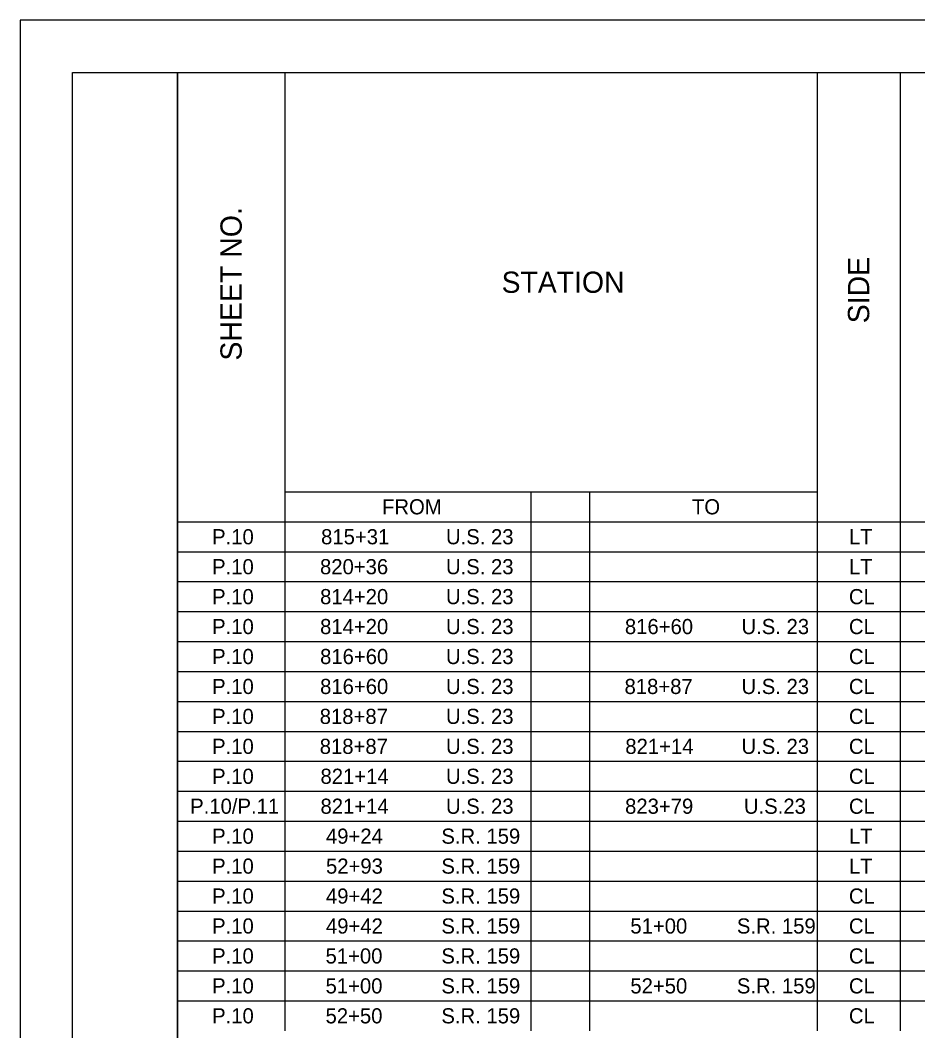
# Model space of a CAD drawing. Extents: x -1022.2 to -988.2, y -965.8 to -943.8.
# Drawn here: x -1022.25 to -1013.68, y -953.43 to -943.79 of the extents above; entities that cross this region are included whole.
import ezdxf

# ---------------------------------------------------------------- set-up
doc = ezdxf.new("R2010")
doc.units = 0
for name, color, linetype in [('Default', 7, 'Continuous'), ('SH_Border', 7, 'Continuous'), ('SH_Cut_Line', 7, 'Continuous')]:
    doc.layers.add(name, color=color, linetype=linetype)

msp = doc.modelspace()

# ---------------------------------------------------------------- linework, layer by layer
at = {"layer": 'Default'}
for p, q in [((-1020.7494, -944.2862), (-1017.3766, -944.2862)), ((-1020.7494, -944.2862), (-1020.7494, -944.5719)), ((-1019.7252, -944.2862), (-1019.7252, -944.5719)), ((-1017.3766, -944.2862), (-1016.8167, -944.2862)), ((-1016.8167, -944.2862), (-1009.047, -944.2862)), ((-1014.6455, -944.2862), (-1014.6455, -944.5719)), ((-1013.8536, -944.2862), (-1013.8536, -944.5719)), ((-1020.7494, -944.5719), (-1020.7494, -944.8577)), ((-1019.7252, -944.5719), (-1019.7252, -944.8577)), ((-1014.6455, -944.5719), (-1014.6455, -944.8577)), ((-1013.8536, -944.5719), (-1013.8536, -944.8577)), ((-1020.7494, -944.8577), (-1020.7494, -945.1434)), ((-1019.7252, -944.8577), (-1019.7252, -945.1434)), ((-1014.6455, -944.8577), (-1014.6455, -945.1434)), ((-1013.8536, -944.8577), (-1013.8536, -945.1434)), ((-1020.7494, -945.1434), (-1020.7494, -945.4292)), ((-1019.7252, -945.1434), (-1019.7252, -945.4292)), ((-1014.6455, -945.1434), (-1014.6455, -945.4292)), ((-1013.8536, -945.1434), (-1013.8536, -945.4292)), ((-1020.7494, -945.4292), (-1020.7494, -945.7149)), ((-1019.7252, -945.4292), (-1019.7252, -945.7149)), ((-1014.6455, -945.4292), (-1014.6455, -945.7149)), ((-1013.8536, -945.4292), (-1013.8536, -945.7149)), ((-1020.7494, -945.7149), (-1020.7494, -946.0006)), ((-1019.7252, -945.7149), (-1019.7252, -946.0006)), ((-1014.6455, -945.7149), (-1014.6455, -946.0006)), ((-1013.8536, -945.7149), (-1013.8536, -946.0006)), ((-1020.7494, -946.0006), (-1020.7494, -946.2864)), ((-1019.7252, -946.0006), (-1019.7252, -946.2864)), ((-1014.6455, -946.0006), (-1014.6455, -946.2864)), ((-1013.8536, -946.0006), (-1013.8536, -946.2864)), ((-1020.7494, -946.2864), (-1020.7494, -946.8578)), ((-1019.7252, -946.2864), (-1019.7252, -946.8578)), ((-1014.6455, -946.2864), (-1014.6455, -946.8578)), ((-1013.8536, -946.2864), (-1013.8536, -946.8578)), ((-1020.7494, -946.8578), (-1020.7494, -947.7151)), ((-1019.7252, -946.8578), (-1019.7252, -947.7151)), ((-1014.6455, -946.8578), (-1014.6455, -947.7151)), ((-1013.8536, -946.8578), (-1013.8536, -947.7151)), ((-1020.7494, -947.7151), (-1020.7494, -948.0008)), ((-1019.7252, -947.7151), (-1019.7252, -948.0008)), ((-1014.6455, -947.7151), (-1014.6455, -948.0008)), ((-1013.8536, -947.7151), (-1013.8536, -948.0008)), ((-1020.7494, -948.0008), (-1020.7494, -948.5723)), ((-1019.7252, -948.0008), (-1019.7252, -948.5723)), ((-1014.6455, -948.0008), (-1014.6455, -948.5723)), ((-1013.8536, -948.0008), (-1013.8536, -948.5723)), ((-1019.7252, -948.2865), (-1017.3766, -948.2865)), ((-1017.3766, -948.2865), (-1016.8167, -948.2865)), ((-1017.3766, -948.2865), (-1017.3766, -948.5723)), ((-1016.8167, -948.2865), (-1014.6455, -948.2865)), ((-1016.8167, -948.2865), (-1016.8167, -948.5723)), ((-1020.7494, -948.5723), (-1017.3766, -948.5723)), ((-1020.7494, -948.5723), (-1020.7494, -948.858)), ((-1019.7252, -948.5723), (-1019.7252, -948.858)), ((-1017.3766, -948.5723), (-1016.8167, -948.5723)), ((-1017.3766, -948.5723), (-1017.3766, -948.858)), ((-1016.8167, -948.5723), (-1009.047, -948.5723)), ((-1016.8167, -948.5723), (-1016.8167, -948.858)), ((-1014.6455, -948.5723), (-1014.6455, -948.858)), ((-1013.8536, -948.5723), (-1013.8536, -948.858)), ((-1020.7494, -948.858), (-1017.3766, -948.858)), ((-1020.7494, -948.858), (-1020.7494, -950.001)), ((-1019.7252, -948.858), (-1019.7252, -950.001)), ((-1017.3766, -948.858), (-1016.8167, -948.858)), ((-1017.3766, -948.858), (-1017.3766, -950.001)), ((-1016.8167, -948.858), (-1009.047, -948.858)), ((-1016.8167, -948.858), (-1016.8167, -950.001)), ((-1014.6455, -948.858), (-1014.6455, -950.001)), ((-1013.8536, -948.858), (-1013.8536, -950.001)), ((-1020.7494, -949.1437), (-1017.3766, -949.1437)), ((-1017.3766, -949.1437), (-1016.8167, -949.1437)), ((-1016.8167, -949.1437), (-1009.047, -949.1437)), ((-1020.7494, -949.4295), (-1017.3766, -949.4295)), ((-1017.3766, -949.4295), (-1016.8167, -949.4295)), ((-1016.8167, -949.4295), (-1009.047, -949.4295)), ((-1020.7494, -949.7152), (-1017.3766, -949.7152)), ((-1017.3766, -949.7152), (-1016.8167, -949.7152)), ((-1016.8167, -949.7152), (-1009.047, -949.7152)), ((-1020.7494, -950.001), (-1017.3766, -950.001)), ((-1020.7494, -950.001), (-1020.7494, -950.2867)), ((-1019.7252, -950.001), (-1019.7252, -950.2867)), ((-1017.3766, -950.001), (-1016.8167, -950.001)), ((-1017.3766, -950.001), (-1017.3766, -950.2867)), ((-1016.8167, -950.001), (-1009.047, -950.001)), ((-1016.8167, -950.001), (-1016.8167, -950.2867)), ((-1014.6455, -950.001), (-1014.6455, -950.2867)), ((-1013.8536, -950.001), (-1013.8536, -950.2867)), ((-1020.7494, -950.2867), (-1017.3766, -950.2867)), ((-1020.7494, -950.2867), (-1020.7494, -950.8582)), ((-1019.7252, -950.2867), (-1019.7252, -950.8582)), ((-1017.3766, -950.2867), (-1016.8167, -950.2867)), ((-1017.3766, -950.2867), (-1017.3766, -950.8582)), ((-1016.8167, -950.2867), (-1009.047, -950.2867)), ((-1016.8167, -950.2867), (-1016.8167, -950.8582)), ((-1014.6455, -950.2867), (-1014.6455, -950.8582)), ((-1013.8536, -950.2867), (-1013.8536, -950.8582)), ((-1020.7494, -950.5724), (-1017.3766, -950.5724)), ((-1017.3766, -950.5724), (-1016.8167, -950.5724)), ((-1016.8167, -950.5724), (-1009.047, -950.5724)), ((-1020.7494, -950.8582), (-1017.3766, -950.8582)), ((-1020.7494, -950.8582), (-1020.7494, -951.4296)), ((-1019.7252, -950.8582), (-1019.7252, -951.4296)), ((-1017.3766, -950.8582), (-1016.8167, -950.8582)), ((-1017.3766, -950.8582), (-1017.3766, -951.4296)), ((-1016.8167, -950.8582), (-1009.047, -950.8582)), ((-1016.8167, -950.8582), (-1016.8167, -951.4296)), ((-1014.6455, -950.8582), (-1014.6455, -951.4296)), ((-1013.8536, -950.8582), (-1013.8536, -951.4296)), ((-1020.7494, -951.1439), (-1017.3766, -951.1439)), ((-1017.3766, -951.1439), (-1016.8167, -951.1439)), ((-1016.8167, -951.1439), (-1009.047, -951.1439)), ((-1020.7494, -951.4296), (-1017.3766, -951.4296)), ((-1020.7494, -951.4296), (-1020.7494, -951.7154)), ((-1019.7252, -951.4296), (-1019.7252, -951.7154)), ((-1017.3766, -951.4296), (-1016.8167, -951.4296)), ((-1017.3766, -951.4296), (-1017.3766, -951.7154)), ((-1016.8167, -951.4296), (-1009.047, -951.4296)), ((-1016.8167, -951.4296), (-1016.8167, -951.7154)), ((-1014.6455, -951.4296), (-1014.6455, -951.7154)), ((-1013.8536, -951.4296), (-1013.8536, -951.7154)), ((-1020.7494, -951.7154), (-1017.3766, -951.7154)), ((-1020.7494, -951.7154), (-1020.7494, -952.2869)), ((-1019.7252, -951.7154), (-1019.7252, -952.2869)), ((-1017.3766, -951.7154), (-1016.8167, -951.7154)), ((-1017.3766, -951.7154), (-1017.3766, -952.2869)), ((-1016.8167, -951.7154), (-1009.047, -951.7154)), ((-1016.8167, -951.7154), (-1016.8167, -952.2869)), ((-1014.6455, -951.7154), (-1014.6455, -952.2869)), ((-1013.8536, -951.7154), (-1013.8536, -952.2869)), ((-1020.7494, -952.0011), (-1017.3766, -952.0011)), ((-1017.3766, -952.0011), (-1016.8167, -952.0011)), ((-1016.8167, -952.0011), (-1009.047, -952.0011)), ((-1020.7494, -952.2869), (-1017.3766, -952.2869)), ((-1020.7494, -952.2869), (-1020.7494, -952.5726)), ((-1019.7252, -952.2869), (-1019.7252, -952.5726)), ((-1017.3766, -952.2869), (-1016.8167, -952.2869)), ((-1017.3766, -952.2869), (-1017.3766, -952.5726)), ((-1016.8167, -952.2869), (-1009.047, -952.2869)), ((-1016.8167, -952.2869), (-1016.8167, -952.5726)), ((-1014.6455, -952.2869), (-1014.6455, -952.5726)), ((-1013.8536, -952.2869), (-1013.8536, -952.5726)), ((-1020.7494, -952.5726), (-1017.3766, -952.5726)), ((-1020.7494, -952.5726), (-1020.7494, -953.4298)), ((-1019.7252, -952.5726), (-1019.7252, -953.4298)), ((-1017.3766, -952.5726), (-1016.8167, -952.5726)), ((-1017.3766, -952.5726), (-1017.3766, -953.4298)), ((-1016.8167, -952.5726), (-1009.047, -952.5726)), ((-1016.8167, -952.5726), (-1016.8167, -953.4298)), ((-1014.6455, -952.5726), (-1014.6455, -953.4298)), ((-1013.8536, -952.5726), (-1013.8536, -953.4298)), ((-1020.7494, -952.8583), (-1017.3766, -952.8583)), ((-1017.3766, -952.8583), (-1016.8167, -952.8583)), ((-1016.8167, -952.8583), (-1009.047, -952.8583)), ((-1020.7494, -953.1441), (-1017.3766, -953.1441)), ((-1017.3766, -953.1441), (-1016.8167, -953.1441)), ((-1016.8167, -953.1441), (-1009.047, -953.1441))]:
    msp.add_line(p, q, dxfattribs=at)
at = {"layer": 'SH_Border'}
for points in [[(-1021.7494, -944.2862), (-1020.7494, -944.2862), (-1020.7494, -965.2862), (-1021.7494, -965.2862)], [(-1020.7494, -944.2862), (-988.7494, -944.2862), (-988.7494, -965.2862), (-1020.7494, -965.2862)]]:
    msp.add_lwpolyline(points, close=True, dxfattribs=at)
at = {"layer": 'SH_Cut_Line'}
msp.add_lwpolyline([(-1022.2494, -965.7862), (-988.2494, -965.7862), (-988.2494, -943.7862), (-1022.2494, -943.7862)], close=True, dxfattribs=at)

# ---------------------------------------------------------------- texts
at = {"layer": 'Default'}
for s, p in [('SHEET NO.', (-1020.1357, -947.0341)), ('SIDE', (-1014.148, -946.6783))]:
    msp.add_text(s, height=0.20312, rotation=90, dxfattribs=at).set_placement(p)
for s, height, p in [('STATION', 0.2024, (-1017.6559, -946.3876)), ('FROM', 0.14457, (-1018.7967, -948.5017)), ('TO', 0.14457, (-1015.8396, -948.5017)), ('P.10', 0.14457, (-1020.4183, -948.7874)), ('815+31', 0.14457, (-1019.3783, -948.7874)), ('U.S. 23', 0.14457, (-1018.1865, -948.7874)), ('LT', 0.14457, (-1014.3414, -948.7874)), ('P.10', 0.14457, (-1020.4183, -949.0732)), ('820+36', 0.14457, (-1019.3886, -949.0732)), ('U.S. 23', 0.14457, (-1018.1865, -949.0732)), ('LT', 0.14457, (-1014.3414, -949.0732)), ('P.10', 0.14457, (-1020.4183, -949.3589)), ('814+20', 0.14457, (-1019.3878, -949.3589)), ('U.S. 23', 0.14457, (-1018.1865, -949.3589)), ('CL', 0.14457, (-1014.3416, -949.3589)), ('P.10', 0.14457, (-1020.4183, -949.6446)), ('814+20', 0.14457, (-1019.3878, -949.6446)), ('U.S. 23', 0.14457, (-1018.1865, -949.6446)), ('816+60', 0.14457, (-1016.4793, -949.6446)), ('U.S. 23', 0.14457, (-1015.3667, -949.6446)), ('CL', 0.14457, (-1014.3416, -949.6446)), ('P.10', 0.14457, (-1020.4183, -949.9304)), ('816+60', 0.14457, (-1019.3878, -949.9304)), ('U.S. 23', 0.14457, (-1018.1865, -949.9304)), ('CL', 0.14457, (-1014.3416, -949.9304)), ('P.10', 0.14457, (-1020.4183, -950.2161)), ('816+60', 0.14457, (-1019.3878, -950.2161)), ('U.S. 23', 0.14457, (-1018.1865, -950.2161)), ('818+87', 0.14457, (-1016.4826, -950.2161)), ('U.S. 23', 0.14457, (-1015.3667, -950.2161)), ('CL', 0.14457, (-1014.3416, -950.2161)), ('P.10', 0.14457, (-1020.4183, -950.5018)), ('818+87', 0.14457, (-1019.3912, -950.5018)), ('U.S. 23', 0.14457, (-1018.1865, -950.5018)), ('CL', 0.14457, (-1014.3416, -950.5018)), ('P.10', 0.14457, (-1020.4183, -950.7876)), ('818+87', 0.14457, (-1019.3912, -950.7876)), ('U.S. 23', 0.14457, (-1018.1865, -950.7876)), ('821+14', 0.14457, (-1016.4755, -950.7876)), ('U.S. 23', 0.14457, (-1015.3667, -950.7876)), ('CL', 0.14457, (-1014.3416, -950.7876)), ('P.10', 0.14457, (-1020.4183, -951.0733)), ('821+14', 0.14457, (-1019.384, -951.0733)), ('U.S. 23', 0.14457, (-1018.1865, -951.0733)), ('CL', 0.14457, (-1014.3416, -951.0733)), ('P.10/P.11', 0.14457, (-1020.6276, -951.3591)), ('821+14', 0.14457, (-1019.384, -951.3591)), ('U.S. 23', 0.14457, (-1018.1865, -951.3591)), ('823+79', 0.14457, (-1016.4776, -951.3591)), ('U.S.23', 0.14457, (-1015.3435, -951.3591)), ('CL', 0.14457, (-1014.3416, -951.3591)), ('P.10', 0.14457, (-1020.4183, -951.6448)), ('49+24', 0.14457, (-1019.3319, -951.6448)), ('S.R. 159', 0.14457, (-1018.2304, -951.6448)), ('LT', 0.14457, (-1014.3414, -951.6448)), ('P.10', 0.14457, (-1020.4183, -951.9305)), ('52+93', 0.14457, (-1019.3316, -951.9305)), ('S.R. 159', 0.14457, (-1018.2304, -951.9305)), ('LT', 0.14457, (-1014.3414, -951.9305)), ('P.10', 0.14457, (-1020.4183, -952.2163)), ('49+42', 0.14457, (-1019.3319, -952.2163)), ('S.R. 159', 0.14457, (-1018.2304, -952.2163)), ('CL', 0.14457, (-1014.3416, -952.2163)), ('P.10', 0.14457, (-1020.4183, -952.502)), ('49+42', 0.14457, (-1019.3319, -952.502)), ('S.R. 159', 0.14457, (-1018.2304, -952.502)), ('51+00', 0.14457, (-1016.4272, -952.502)), ('S.R. 159', 0.14457, (-1015.4106, -952.502)), ('CL', 0.14457, (-1014.3416, -952.502)), ('P.10', 0.14457, (-1020.4183, -952.7877)), ('51+00', 0.14457, (-1019.3357, -952.7877)), ('S.R. 159', 0.14457, (-1018.2304, -952.7877)), ('CL', 0.14457, (-1014.3416, -952.7877)), ('P.10', 0.14457, (-1020.4183, -953.0735)), ('51+00', 0.14457, (-1019.3357, -953.0735)), ('S.R. 159', 0.14457, (-1018.2304, -953.0735)), ('52+50', 0.14457, (-1016.4272, -953.0735)), ('S.R. 159', 0.14457, (-1015.4106, -953.0735)), ('CL', 0.14457, (-1014.3416, -953.0735)), ('P.10', 0.14457, (-1020.4183, -953.3592)), ('52+50', 0.14457, (-1019.3357, -953.3592)), ('S.R. 159', 0.14457, (-1018.2304, -953.3592)), ('CL', 0.14457, (-1014.3416, -953.3592))]:
    msp.add_text(s, height=height, dxfattribs=at).set_placement(p)

doc.saveas('drawing.dxf')
